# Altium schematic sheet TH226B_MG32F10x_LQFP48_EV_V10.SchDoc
size 309 x 233 mm
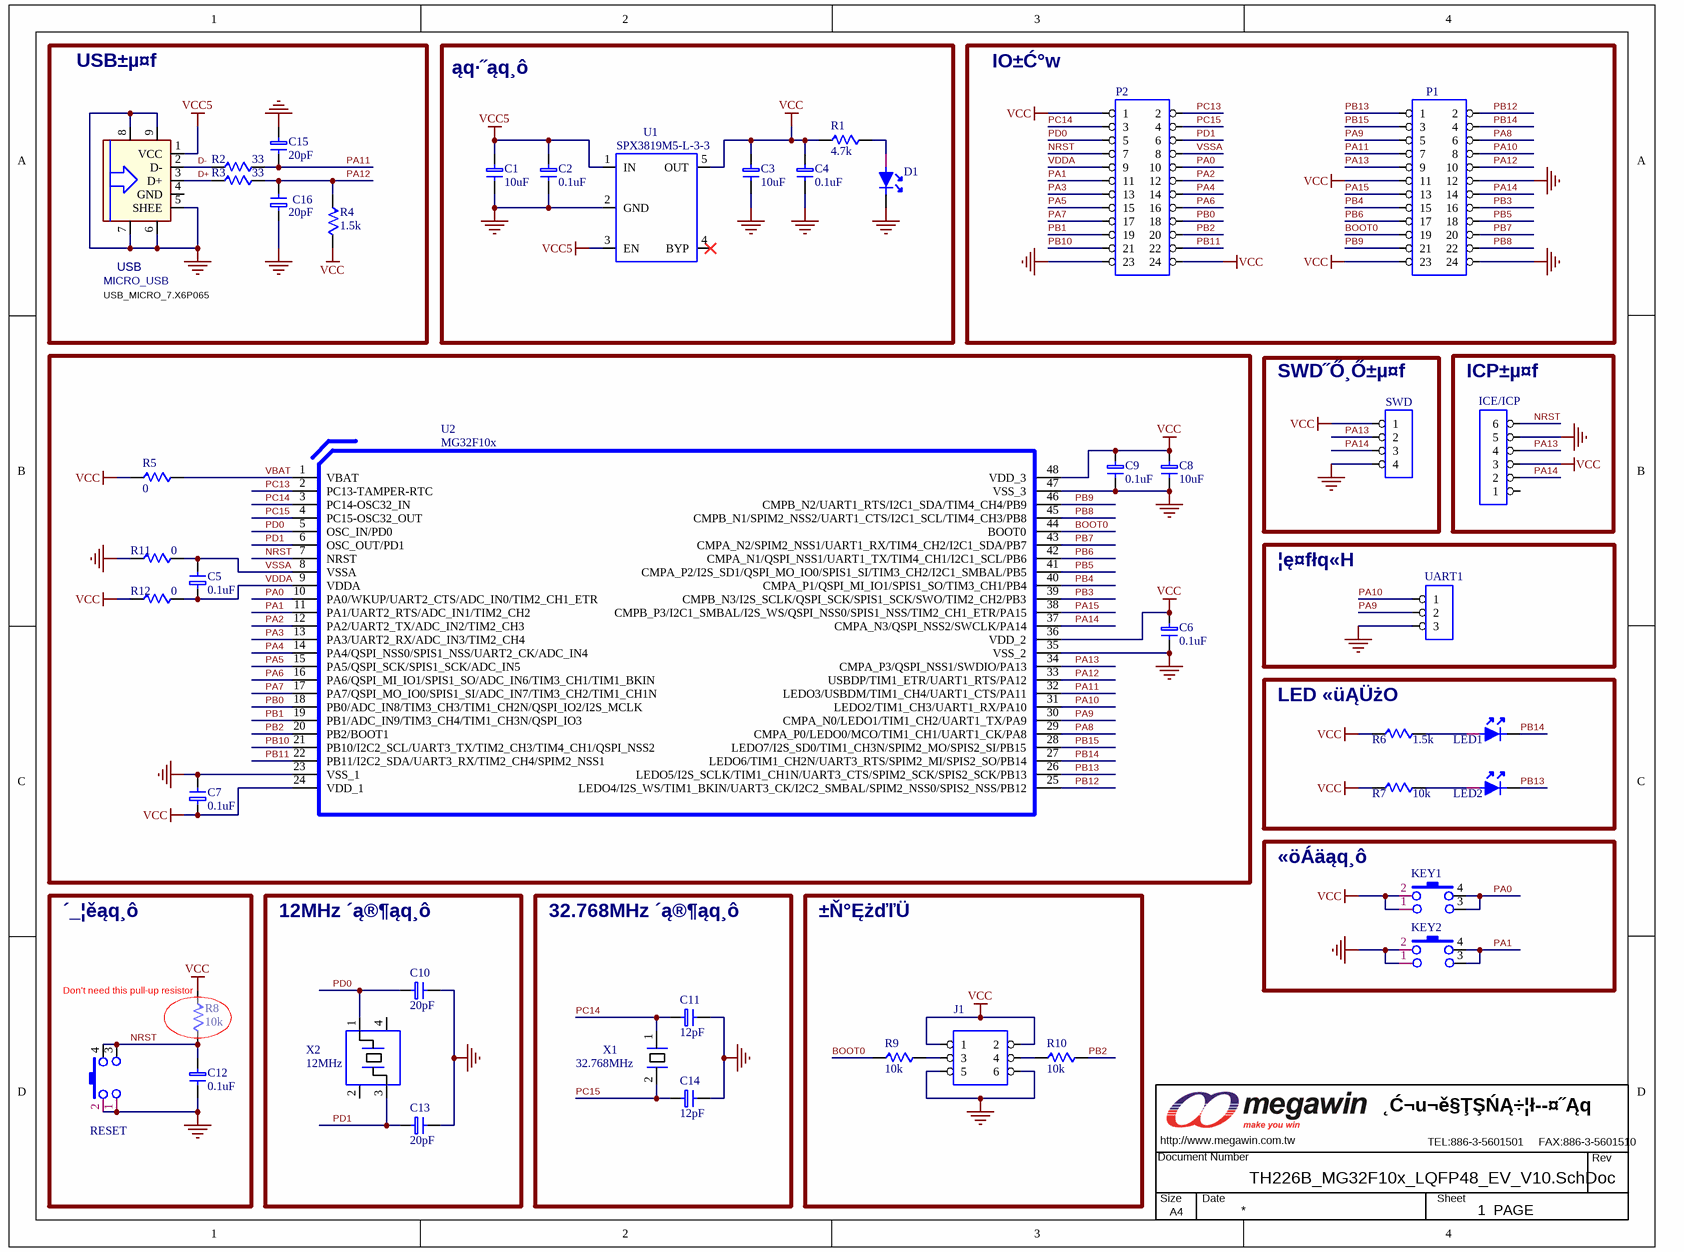
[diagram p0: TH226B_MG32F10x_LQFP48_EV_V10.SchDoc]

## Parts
C1  10uF  [C0805]
C2  0.1uF  [C0603]
C3  10uF  [C0805]
C4  0.1uF  [C0603]
C5  0.1uF  [C0603]
C6  0.1uF  [C0603]
C7  0.1uF  [C0603]
C8  10uF  [C0805]
C9  0.1uF  [C0603]
C10  20pF  [C0603]
C11  12pF  [C0603]
C12  0.1uF  [C0603]
C13  20pF  [C0603]
C14  12pF  [C0603]
C15  20pF  [C0603]
C16  20pF  [C0603]
D1  (no value)  [LED0805_RED]
ICE/ICP  (no value)  [PS6P254F_90]
J1  CON3X2  [HDR-M-2.54_2X3]  (value not drawn)
KEY1  SW-PB4  [KEY-TH_4P-L6.0-W6.0-P4.50-LS6.5]  (value not drawn)
KEY2  SW-PB4  [KEY-TH_4P-L6.0-W6.0-P4.50-LS6.5]  (value not drawn)
LED1  (no value)  [LED0805_RED]
LED2  (no value)  [LED0805_GREEN]
MW1  MW-A4  [MEGAWIN_3.4]  (value not drawn)  (no BOM)
P1  CON12X2  [HDR-TH_24P-P2.54-V-R2-C12-S2.54]  (value not drawn)
P2  CON12X2  [HDR-TH_24P-P2.54-V-R2-C12-S2.54]  (value not drawn)
R1  4.7k  [R0603]
R2  33  [R0603]
R3  33  [R0603]
R4  1.5k  [R0603]
R5  0  [R0603]
R6  1.5k  [R0603]
R7  10k  [R0603]
R8  10k  [R0603]
R9  10k  [R0603]
R10  10k  [R0603]
R11  0  [R0603-1]
R12  0  [R0603-1]
RESET  SW-PB4  [KEY-TH_4P-L6.0-W6.0-P4.50-LS6.5]  (value not drawn)
SWD  CON4  [HDR-M-2.54_1X4]  (value not drawn)
U1  SPX3819M5-L-3-3  [SOT-23-5_L3.0-W1.7-P0.95-LS2.8-TL]
U2  MG32F10x  [LQFP-48_L7.0-W7.0-P0.50-LS9.0-BL]
UART1  CON3  [HDR-M-2.54_1X3]  (value not drawn)
USB  MICRO_USB  [USB5-micro_B-«Ř­ĘMRUSB-5B-D17xx-]
X1  32.768MHz  [OSC-SMD_L3.2-W1.5]
X2  12MHz  [OSC-SMD_4P-L2.5-W2.0-BL]

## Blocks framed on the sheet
USB±µ¤f: C15 C16 R2-R4 USB
ąq·˝ąq¸ô: C1-C4 D1 R1 U1
IO±Ć°w: P1 P2
SWD˝Ő¸Ő±µ¤f: SWD
ICP±µ¤f: ICE/ICP
¦ę¤fłq«H: UART1
LED «üĄÜżO: LED1 LED2 R6 R7
«öÁäąq¸ô: KEY1 KEY2
´_¦ěąq¸ô: C12 R8 RESET
12MHz ´ą®¶ąq¸ô: C10 C13 X2
32.768MHz ´ą®¶ąq¸ô: C11 C14 X1
±Ň°ĘżďľÜ: J1 R9 R10

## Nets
GND_POWER: C1.2 C2.2 C3.2 C4.2 C6.2 C7.2 C8.2 C9.2 C10.2 C11.2 C12.2 C13.2 C14.2 C15.1 C16.1 D1.2 ICE/ICP.5 J1.5 J1.6 KEY2.1 KEY2.2 P1.12 P1.24 P2.23 R11.1 RESET.1 RESET.2 SWD.4 U1.2(GND) U2.23(VSS_1) U2.35(VSS_2) U2.47(VSS_3) UART1.3 USB.5(SHEE) USB.6 USB.7 USB.8 USB.9
VCC: C3.1 C4.1 C6.1 C7.1 C8.1 C9.1 ICE/ICP.3 J1.1 J1.2 KEY1.1 KEY1.2 P1.11 P1.23 P2.1 P2.24 R1.1 R4.2 R5.1 R6.1 R7.1 R8.1 R12.1 SWD.1 U1.5(OUT) U2.24(VDD_1) U2.36(VDD_2) U2.48(VDD_3)
VCC5: C1.1 C2.1 U1.1(IN) U1.3(EN) USB.1(VCC)
BOOT0: P1.19 R9.1 U2.44(BOOT0)
D+: R3.1 USB.3(D+)
D-: R2.1 USB.2(D-)
NRST: C12.1 ICE/ICP.6 P2.7 R8.2 RESET.3 RESET.4 U2.7(NRST)
PA0: KEY1.3 KEY1.4 P2.10 U2.10(PA0/WKUP/UART2_CTS/ADC_IN0/TIM2_CH1_ETR)
PA1: KEY2.3 KEY2.4 P2.11 U2.11(PA1/UART2_RTS/ADC_IN1/TIM2_CH2)
PA2: P2.12 U2.12(PA2/UART2_TX/ADC_IN2/TIM2_CH3)
PA3: P2.13 U2.13(PA3/UART2_RX/ADC_IN3/TIM2_CH4)
PA4: P2.14 U2.14(PA4/QSPI_NSS0/SPIS1_NSS/UART2_CK/ADC_IN4)
PA5: P2.15 U2.15(PA5/QSPI_SCK/SPIS1_SCK/ADC_IN5)
PA6: P2.16 U2.16(PA6/QSPI_MI_IO1/SPIS1_SO/ADC_IN6/TIM3_CH1/TIM1_BKIN)
PA7: P2.17 U2.17(PA7/QSPI_MO_IO0/SPIS1_SI/ADC_IN7/TIM3_CH2/TIM1_CH1N)
PA8: P1.6 U2.29(CMPA_P0/LEDO0/MCO/TIM1_CH1/UART1_CK/PA8)
PA9: P1.5 U2.30(CMPA_N0/LEDO1/TIM1_CH2/UART1_TX/PA9) UART1.2
PA10: P1.8 U2.31(LEDO2/TIM1_CH3/UART1_RX/PA10) UART1.1
PA11: C15.2 P1.7 R2.2 U2.32(LEDO3/USBDM/TIM1_CH4/UART1_CTS/PA11)
PA12: C16.2 P1.10 R3.2 R4.1 U2.33(USBDP/TIM1_ETR/UART1_RTS/PA12)
PA13: ICE/ICP.4 P1.9 SWD.2 U2.34(CMPA_P3/QSPI_NSS1/SWDIO/PA13)
PA14: ICE/ICP.2 P1.14 SWD.3 U2.37(CMPA_N3/QSPI_NSS2/SWCLK/PA14)
PA15: P1.13 U2.38(CMPB_P3/I2C1_SMBAL/I2S_WS/QSPI_NSS0/SPIS1_NSS/TIM2_CH1_ETR/PA15)
PB0: P2.18 U2.18(PB0/ADC_IN8/TIM3_CH3/TIM1_CH2N/QSPI_IO2/I2S_MCLK)
PB1: P2.19 U2.19(PB1/ADC_IN9/TIM3_CH4/TIM1_CH3N/QSPI_IO3)
PB2: P2.20 R10.2 U2.20(PB2/BOOT1)
PB3: P1.16 U2.39(CMPB_N3/I2S_SCLK/QSPI_SCK/SPIS1_SCK/SWO/TIM2_CH2/PB3)
PB4: P1.15 U2.40(CMPA_P1/QSPI_MI_IO1/SPIS1_SO/TIM3_CH1/PB4)
PB5: P1.18 U2.41(CMPA_P2/I2S_SD1/QSPI_MO_IO0/SPIS1_SI/TIM3_CH2/I2C1_SMBAL/PB5)
PB6: P1.17 U2.42(CMPA_N1/QSPI_NSS1/UART1_TX/TIM4_CH1/I2C1_SCL/PB6)
PB7: P1.20 U2.43(CMPA_N2/SPIM2_NSS1/UART1_RX/TIM4_CH2/I2C1_SDA/PB7)
PB8: P1.22 U2.45(CMPB_N1/SPIM2_NSS2/UART1_CTS/I2C1_SCL/TIM4_CH3/PB8)
PB9: P1.21 U2.46(CMPB_N2/UART1_RTS/I2C1_SDA/TIM4_CH4/PB9)
PB10: P2.21 U2.21(PB10/I2C2_SCL/UART3_TX/TIM2_CH3/TIM4_CH1/QSPI_NSS2)
PB11: P2.22 U2.22(PB11/I2C2_SDA/UART3_RX/TIM2_CH4/SPIM2_NSS1)
PB12: P1.2 U2.25(LEDO4/I2S_WS/TIM1_BKIN/UART3_CK/I2C2_SMBAL/SPIM2_NSS0/SPIS2_NSS/PB12)
PB13: LED2.2 P1.1 U2.26(LEDO5/I2S_SCLK/TIM1_CH1N/UART3_CTS/SPIM2_SCK/SPIS2_SCK/PB13)
PB14: LED1.2 P1.4 U2.27(LEDO6/TIM1_CH2N/UART3_RTS/SPIM2_MI/SPIS2_SO/PB14)
PB15: P1.3 U2.28(LEDO7/I2S_SD0/TIM1_CH3N/SPIM2_MO/SPIS2_SI/PB15)
PC13: P2.2 U2.2(PC13-TAMPER-RTC)
PC14: C11.1 P2.3 U2.3(PC14-OSC32_IN) X1.1
PC15: C14.1 P2.4 U2.4(PC15-OSC32_OUT) X1.2
PD0: C10.1 P2.5 U2.5(OSC_IN/PD0) X2.1
PD1: C13.1 P2.6 U2.6(OSC_OUT/PD1) X2.3
VBAT: R5.2 U2.1(VBAT)
VDDA: C5.1 P2.9 R12.2 U2.9(VDDA)
VSSA: C5.2 P2.8 R11.2 U2.8(VSSA)
NetD1_1: D1.1 R1.2
NetJ1_3: J1.3 R9.2
NetJ1_4: J1.4 R10.1
NetLED1_1: LED1.1 R6.2
NetLED2_1: LED2.1 R7.2

Not connected (* = marked no-connect by the designer): ICE/ICP 1; U1 4(BYP)*; USB 4(GND); X2 2 4

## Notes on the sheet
- USB_MICRO_7.X6P065
- (near R8) Don't need this pull-up resistor

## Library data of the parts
C1-C16 = CAP: Capacitor
D1 LED1 LED2 = LED_SC
ICE/ICP = CON6: Connector
MW1 = MW_A4
R1-R12 = RES1
SWD = CON4: Connector
U1 = IC5_SPX3819M5-L-3-3
U2 = IC48_MG32F10x
UART1 = CON3: Connector
USB = USB_Micro
X1 = XTAL: Crystal
X2 = X3P_1: Crystal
